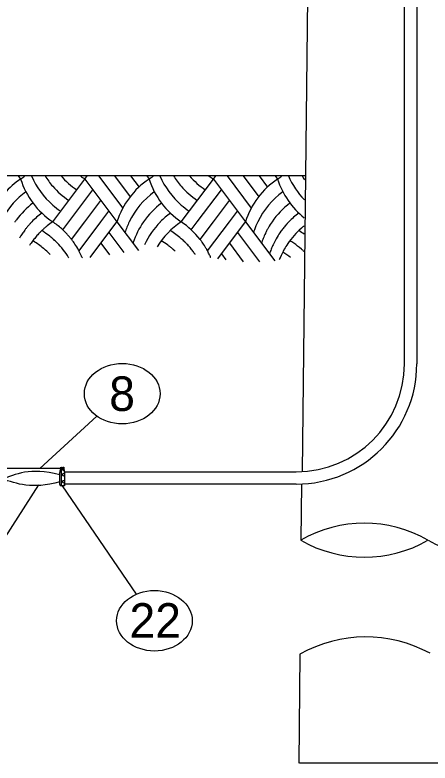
# Model space of a CAD drawing. Extents: x 99862 to 104211, y 98939 to 102076.
# Drawn here: x 100788.5 to 100980.3, y 100737.8 to 101084 of the extents above; entities that cross this region are included whole.
import ezdxf

# ---------------------------------------------------------------- set-up
doc = ezdxf.new("R2010")
doc.units = 0
for name, color, linetype in [('Level 1', 7, 'Continuous'), ('Level 11', 7, 'Continuous'), ('Level 13', 7, 'Continuous'), ('Level 15', 7, 'Continuous'), ('Level 20', 7, 'Continuous'), ('Level 8', 7, 'Continuous')]:
    doc.layers.add(name, color=color, linetype=linetype)

msp = doc.modelspace()

# ---------------------------------------------------------------- linework, layer by layer
at = {"layer": 'Level 1'}
for p, q in [((100926.3, 101340.94), (100921.22, 100872.66)), ((100920.83, 100866.94), (100920.54, 100840.89)), ((100920.19, 100788.16), (100919.64, 100737.77)), ((101039.34, 100737.77), (100919.97, 100737.77))]:
    msp.add_line(p, q, dxfattribs=at)
for centre, radius, start, end in [((100949.95, 100789.95), 58.82, 60, 120), ((100949.95, 100891.83), 58.82, 240, 300), ((101009.33, 100895.15), 61.98, 241.0943, 298.3599), ((100950.61, 100734.16), 61.98, 61.3761, 119.3926)]:
    msp.add_arc(centre, radius, start, end, dxfattribs=at)
at = {"layer": 'Level 11'}
msp.add_line((100810.77, 100874.11), (100755.06, 100874.11), dxfattribs=at)
for points in [[(100809.24, 100871.12), (100794.89, 100874.79), (100783.46, 100867.92), (100766.15, 100865.27), (100752.4, 100866.99)], [(100809.24, 100867.94), (100796.06, 100864.31), (100783.06, 100869.64), (100766.93, 100873.64), (100754.71, 100872.33)]]:
    msp.add_open_spline(points, degree=3, dxfattribs=at)
at = {"layer": 'Level 13'}
for p, q in [((100922.38, 101009.51), (100767.83, 101009.51)), ((100789.96, 101009.51), (100791.06, 101008.05)), ((100820.75, 101008.05), (100821.85, 101009.51)), ((100827.08, 101009.51), (100838.28, 100994.58)), ((100834.5, 101009.51), (100841.72, 100999.89)), ((100841.93, 101009.51), (100845.8, 101004.35)), ((100849.35, 101009.51), (100850.45, 101008.05)), ((100880.15, 101008.05), (100881.25, 101009.51)), ((100886.48, 101009.51), (100897.67, 100994.58)), ((100893.9, 101009.51), (100901.12, 100999.89)), ((100901.32, 101009.51), (100905.19, 101004.35)), ((100908.75, 101009.51), (100909.85, 101008.05)), ((100805.9, 100988.25), (100820.75, 101008.05)), ((100820.75, 101008.05), (100835.6, 100988.25)), ((100865.3, 100988.25), (100880.15, 101008.05)), ((100880.15, 101008.05), (100895, 100988.25)), ((100813.33, 100988.25), (100824.46, 101003.1)), ((100872.72, 100988.25), (100883.86, 101003.1)), ((100820.75, 100988.25), (100828.18, 100998.15)), ((100880.15, 100988.25), (100887.57, 100998.15)), ((100828.18, 100988.25), (100831.89, 100993.2)), ((100887.57, 100988.25), (100891.29, 100993.2)), ((100810.56, 100984.55), (100813.33, 100988.25)), ((100814.63, 100980.09), (100820.75, 100988.25)), ((100818.08, 100974.78), (100828.18, 100988.25)), ((100823.24, 100971.77), (100835.6, 100988.25)), ((100835.6, 100988.25), (100845.57, 100974.95)), ((100869.95, 100984.55), (100872.72, 100988.25)), ((100874.03, 100980.09), (100880.15, 100988.25)), ((100877.47, 100974.78), (100887.57, 100988.25)), ((100882.19, 100971.16), (100895, 100988.25)), ((100895, 100988.25), (100908.52, 100970.22)), ((100831.89, 100983.3), (100838.84, 100974.03)), ((100891.29, 100983.3), (100901.51, 100969.67)), ((100828.18, 100978.35), (100832.23, 100972.94)), ((100887.57, 100978.35), (100894, 100969.78)), ((100883.86, 100973.4), (100885.96, 100970.6))]:
    msp.add_line(p, q, dxfattribs=at)
for centre, start, end in [((100770.09, 101039.23), 303.9036, 307.7198), ((100830.58, 101024.38), 203.3189, 228.9599), ((100834.29, 101029.33), 211.8414, 220.9416), ((100838, 101034.28), 221.2458, 236.0964), ((100841.71, 101039.23), 232.2802, 236.0964), ((100829.49, 101039.23), 303.9036, 307.7198), ((100889.97, 101024.38), 203.3189, 228.9599), ((100893.69, 101029.33), 211.8414, 220.9416), ((100897.4, 101034.28), 221.2458, 236.0964), ((100901.11, 101039.23), 232.2802, 236.0964), ((100888.89, 101039.23), 303.9036, 307.7198), ((100949.37, 101024.38), 203.3189, 223.8171), ((100953.08, 101029.33), 211.8414, 215.1502), ((100812.02, 100976.86), 123.9036, 153.87), ((100826.86, 101019.44), 197.6434, 236.0964), ((100871.41, 100976.86), 123.9036, 162.3566), ((100886.26, 101019.44), 197.6434, 236.0964), ((100930.81, 100976.86), 123.9036, 162.3566), ((100945.66, 101019.44), 197.6434, 231.3067), ((100834.29, 101029.33), 220.9415, 236.0964), ((100893.68, 101029.33), 220.9415, 236.0964), ((100815.73, 100971.91), 126.3063, 150.6014), ((100875.12, 100971.91), 126.3063, 154.2266), ((100934.52, 100971.91), 126.3063, 154.2266), ((100819.44, 100966.96), 127.1006, 143.7806), ((100830.58, 101024.38), 228.9599, 236.0964), ((100878.84, 100966.96), 127.1006, 145.4911), ((100889.97, 101024.38), 228.9599, 236.0964), ((100938.23, 100966.96), 127.1006, 145.4911), ((100823.15, 100962.01), 126.331, 135.7128), ((100882.55, 100962.01), 126.331, 135.7128), ((100941.94, 100962.01), 126.331, 135.7128), ((100819.44, 100966.96), 143.7806, 144.8078), ((100819.44, 100966.96), 145.491, 145.8701), ((100819.44, 100966.96), 144.8078, 145.4911), ((100823.15, 100962.01), 141.2961, 143.3576), ((100823.15, 100962.01), 138.9819, 141.2961), ((100823.15, 100962.01), 138.6172, 138.9819), ((100823.15, 100962.01), 137.5644, 138.6172), ((100823.15, 100962.01), 136.5512, 137.5644), ((100823.15, 100962.01), 135.7127, 136.5512), ((100826.86, 100957.06), 131.1039, 133.3874), ((100826.86, 100957.06), 130.7555, 131.1039), ((100826.86, 100957.06), 129.6968, 130.7555), ((100826.86, 100957.06), 128.6838, 129.6968), ((100826.86, 100957.06), 123.9036, 128.6838), ((100784.94, 100957.06), 48.3035, 56.0963), ((100875.12, 100971.91), 154.2265, 162.3566), ((100878.84, 100966.96), 145.491, 161.845), ((100882.55, 100962.01), 135.7127, 155.4077), ((100886.26, 100957.06), 123.9036, 148.4771), ((100844.34, 100957.06), 37.9022, 56.0963), ((100934.52, 100971.91), 154.2265, 160.398), ((100938.23, 100966.96), 150.1753, 152.3998), ((100938.23, 100966.96), 145.491, 150.1753), ((100941.94, 100962.01), 141.1365, 144.1293), ((100941.94, 100962.01), 138.1128, 141.1365), ((100941.94, 100962.01), 135.7127, 138.1128), ((100945.66, 100957.06), 131.1496, 131.6493), ((100945.66, 100957.06), 128.7729, 131.1496), ((100823.15, 100962.01), 148.1962, 150.1022), ((100823.15, 100962.01), 146.7085, 148.1962), ((100823.15, 100962.01), 143.3576, 146.7085), ((100826.86, 100957.06), 138.7045, 140.3907), ((100826.86, 100957.06), 135.5233, 138.7045), ((100826.86, 100957.06), 133.3874, 135.5233), ((100781.23, 100952.11), 55.3019, 58.5465), ((100781.23, 100952.11), 50.5554, 55.3019), ((100784.94, 100957.06), 46.9713, 48.3035), ((100784.94, 100957.06), 45.6421, 46.9713), ((100784.94, 100957.06), 45.2535, 45.6421), ((100784.94, 100957.06), 42.7287, 45.2535), ((100784.94, 100957.06), 40.315, 42.7287), ((100840.63, 100952.11), 48.9597, 58.5465), ((100934.52, 100971.91), 162.2011, 162.3566), ((100934.52, 100971.91), 160.398, 162.2011), ((100938.23, 100966.96), 154.8929, 158.7707), ((100938.23, 100966.96), 154.7134, 154.8929), ((100938.23, 100966.96), 152.3998, 154.7134), ((100941.94, 100962.01), 144.4124, 149.3066), ((100941.94, 100962.01), 144.1293, 144.4124), ((100945.66, 100957.06), 138.5057, 145.8624), ((100945.66, 100957.06), 131.6493, 138.5057), ((100900.02, 100952.11), 54.0525, 58.5465), ((100826.86, 100957.06), 143.69, 147.3289), ((100826.86, 100957.06), 140.3907, 143.69), ((100777.52, 100947.16), 58.7393, 59.3021), ((100777.52, 100947.16), 50.0719, 58.7393), ((100781.23, 100952.11), 48.9597, 50.5554), ((100781.23, 100952.11), 47.9379, 48.9597), ((100781.23, 100952.11), 44.708, 47.9379), ((100781.23, 100952.11), 38.2327, 44.708), ((100784.94, 100957.06), 37.7218, 40.315), ((100784.94, 100957.06), 35.586, 37.7218), ((100784.94, 100957.06), 33.8504, 35.586), ((100878.84, 100966.96), 162.1847, 162.3566), ((100878.84, 100966.96), 161.845, 162.1847), ((100836.92, 100947.16), 53.95, 59.3021), ((100840.63, 100952.11), 45.5186, 48.9597), ((100840.63, 100952.11), 44.5439, 45.5186), ((100840.63, 100952.11), 43.5026, 44.5439), ((100844.34, 100957.06), 36.8054, 37.9022), ((100844.34, 100957.06), 35.5899, 36.8054), ((100844.34, 100957.06), 35.5088, 35.5899), ((100844.34, 100957.06), 33.655, 35.5088), ((100938.23, 100966.96), 158.7707, 162.3566), ((100941.94, 100962.01), 149.3066, 155.3621), ((100896.31, 100947.16), 56.0684, 59.3021), ((100896.31, 100947.16), 49.181, 56.0684), ((100777.52, 100947.16), 48.1463, 50.0719), ((100777.52, 100947.16), 43.6549, 48.1463), ((100781.23, 100952.11), 37.8769, 38.2327), ((100781.23, 100952.11), 31.6366, 37.8769), ((100784.94, 100957.06), 28.878, 33.8504), ((100784.94, 100957.06), 28.3028, 28.878), ((100784.94, 100957.06), 24.1031, 28.3028), ((100836.92, 100947.16), 53.1241, 53.95), ((100836.92, 100947.16), 52.3044, 53.1241), ((100836.92, 100947.16), 52.0458, 52.3044), ((100836.92, 100947.16), 51.126, 52.0458), ((100836.92, 100947.16), 48.661, 51.126), ((100836.92, 100947.16), 47.0235, 49.5359), ((100836.92, 100947.16), 47.7208, 48.661), ((100836.92, 100947.16), 47.5307, 47.7208), ((100836.92, 100947.16), 47.479, 47.5307), ((100836.92, 100947.16), 47.2677, 47.479), ((100840.63, 100952.11), 43.3492, 43.5026), ((100840.63, 100952.11), 41.8941, 43.3492), ((100840.63, 100952.11), 38.3116, 41.8941), ((100840.63, 100952.11), 37.6464, 38.3116), ((100840.63, 100952.11), 36.182, 37.6464), ((100844.34, 100957.06), 29.4386, 33.655), ((100844.34, 100957.06), 29.2698, 29.4386), ((100844.34, 100957.06), 26.4898, 29.2698), ((100941.94, 100962.01), 158.8873, 162.3566), ((100941.94, 100962.01), 155.3621, 158.8873), ((100945.66, 100957.06), 150.4925, 157.2485), ((100945.66, 100957.06), 145.8624, 150.4925), ((100896.31, 100947.16), 46.8792, 49.181), ((100781.23, 100952.11), 31.3198, 31.6366), ((100784.94, 100957.06), 22.6264, 24.1031), ((100836.92, 100947.16), 47.1421, 47.2677), ((100836.92, 100947.16), 47.0984, 47.1421), ((100840.63, 100952.11), 34.9771, 36.182), ((100840.63, 100952.11), 34.2077, 34.9771), ((100840.63, 100952.11), 33.978, 34.2077), ((100840.63, 100952.11), 33.9518, 33.978), ((100844.34, 100957.06), 24.8644, 26.4898), ((100844.34, 100957.06), 23.6321, 24.8644), ((100844.34, 100957.06), 23.1986, 23.6321), ((100844.34, 100957.06), 23.011, 23.1986), ((100945.66, 100957.06), 157.5308, 158.847), ((100945.66, 100957.06), 157.2485, 157.5308), ((100892.6, 100942.21), 51.7329, 58.4874)]:
    msp.add_arc(centre, 37.58, start, end, dxfattribs=at)
at = {"layer": 'Level 15'}
for p, q in [((100826.3, 100898.33), (100799.94, 100874.11)), ((100767.13, 100816.02), (100799.54, 100866.56)), ((100844.56, 100815.92), (100810.42, 100866.01))]:
    msp.add_line(p, q, dxfattribs=at)
at = {"layer": 'Level 20'}
for centre in [(100838.03, 100908.72), (100852.92, 100803.62)]:
    msp.add_ellipse(centre, major_axis=(-17.5, 0), ratio=0.8, dxfattribs=at)
at = {"layer": 'Level 8'}
for p, q in [((100968.49, 100922.59), (100968.49, 101197.66)), ((100974.19, 101197.66), (100974.19, 100922.59)), ((100809.85, 100874.42), (100809.4, 100874.42)), ((100809.4, 100874.42), (100809.4, 100874.19)), ((100809.85, 100873.5), (100809.85, 100874.72)), ((100810, 100874.72), (100810, 100873.65)), ((100810.61, 100874.42), (100810, 100874.42)), ((100810.92, 100874.42), (100810.77, 100874.42)), ((100810.92, 100873.65), (100810.92, 100874.42)), ((100809.24, 100872.87), (100809.24, 100872.22)), ((100809.24, 100866.61), (100809.24, 100872.22)), ((100809.4, 100874.19), (100809.62, 100874.19)), ((100809.62, 100874.03), (100809.4, 100874.03)), ((100809.4, 100874.03), (100809.4, 100873.8)), ((100809.4, 100873.8), (100809.85, 100873.8)), ((100809.84, 100874.25), (100809.84, 100866.01)), ((100810.12, 100873.47), (100809.84, 100873.47)), ((100810, 100873.8), (100810.61, 100873.8)), ((100810, 100873.65), (100810.92, 100873.65)), ((100810.46, 100873.47), (100810.12, 100873.47)), ((100811.34, 100873.47), (100810.46, 100873.47)), ((100811.34, 100872.22), (100811.34, 100873.47)), ((100811.34, 100872.59), (100918.49, 100872.59)), ((100811.34, 100872.22), (100811.34, 100866.01)), ((100810.12, 100866.01), (100809.84, 100866.01)), ((100810.46, 100866.01), (100810.12, 100866.01)), ((100811.34, 100866.01), (100810.46, 100866.01)), ((100918.49, 100866.89), (100811.34, 100866.89))]:
    msp.add_line(p, q, dxfattribs=at)
for points in [[(100809.85, 100874.72), (100810, 100874.72)], [(100810.61, 100873.8), (100810.61, 100874.42)], [(100810.77, 100874.72), (100811.08, 100874.72)], [(100811.08, 100874.72), (100811.08, 100873.5)], [(100809.62, 100874.19), (100809.62, 100874.03)], [(100810.77, 100873.5), (100809.85, 100873.5)], [(100811.08, 100873.5), (100810.77, 100873.5)]]:
    msp.add_lwpolyline(points, dxfattribs=at)
msp.add_circle((100810.77, 100874.11), 0.154, dxfattribs=at)
for centre, radius, start, end in [((100918.49, 100922.59), 50, 270, 360), ((100918.49, 100922.59), 55.7, 269.9968, 359.9968), ((100810.77, 100874.57), 0.153, 90, 180), ((100810.77, 100874.57), 0.153, 180, 270), ((100809.84, 100872.87), 0.6, 90, 180), ((100809.84, 100866.61), 0.6, 180, 270)]:
    msp.add_arc(centre, radius, start, end, dxfattribs=at)
for centre, start_param, end_param in [((100811.35, 100871.22), 2.765553, 3.678356), ((100811.35, 100871.22), 2.316251, 2.765553), ((100811.35, 100873.7), 3.632714, 4.703498), ((100811.35, 100871.22), 3.678356, 4.123731), ((100811.35, 100871.22), 1.579687, 2.316251), ((100811.35, 100867.95), 2.765553, 3.678356), ((100811.35, 100867.95), 2.316251, 2.765553), ((100811.35, 100867.95), 3.678356, 4.123731), ((100811.35, 100867.95), 1.579687, 2.316251), ((100811.35, 100871.22), 4.126463, 4.703498), ((100811.35, 100867.95), 4.126463, 4.703498), ((100811.35, 100865.78), 1.579687, 2.650471)]:
    msp.add_ellipse(centre, major_axis=(1.06, 0), ratio=0.470588, start_param=start_param, end_param=end_param, dxfattribs=at)

# ---------------------------------------------------------------- texts
at = {"layer": 'Level 20'}
for s, p in [('8', (100832.02, 100900.72)), ('22', (100841.38, 100795.75))]:
    msp.add_text(s, height=16, dxfattribs=at).set_placement(p)

doc.saveas('drawing.dxf')
